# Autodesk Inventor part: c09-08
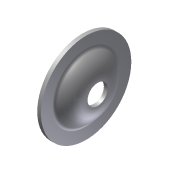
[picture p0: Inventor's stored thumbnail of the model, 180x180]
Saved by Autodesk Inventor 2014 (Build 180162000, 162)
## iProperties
Created: 2010-12
Part Number: c09-08
Document SubType Name: Modeling
Designer: Thom Tremblay
Density: 1 g/cm^3
Material: Generic
Appearance: Steel
Author: Thom Tremblay
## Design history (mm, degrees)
sketch "Sketch1"
  geometry: L1 (-1.246, 28.575)-(-1.246, 21.449); L2 (6.025, 7.188)-(6.025, 6.35); L3 (0, 0)-(18.611, 0); L4 (1.135, 28.575)-(1.135, 21.449); L5 (8.406, 7.188)-(8.406, 6.35); L6 (8.406, 6.35)-(6.025, 6.35); L7 (-1.246, 28.575)-(1.135, 28.575); A1 r 4.921 centre (3.675, 21.449) between (-1.246, 21.449) and (0.785, 17.467); A2 r 12.7 centre (-6.675, 7.188) between (6.025, 7.188) and (0.785, 17.467); A3 r 2.54 centre (3.675, 21.449) between (1.135, 21.449) and (2.183, 19.394); A4 r 15.081 centre (-6.675, 7.188) between (8.406, 7.188) and (2.183, 19.394)
  constraints: 14 end point, 8 point on circle, 5 tangent, 4 centre point, 3 parallel, 2 perpendicular, 1 vertical, 2 other
  dimensions: "d0" = 2.38125 distance between parallel lines of L4 L1; "d1" = 57.15 diameter of L1.start L3; "d2" = 12.7 diameter of L5.end L3; "d3" = 9.652 distance between parallel lines of L1 L5; "d4" = 12.7 radius of A2; "d5" = 2.54 radius of A3
revolve "Revolution1" sketch "Sketch1" stored, may be unused: angle "d6" = 90 deg
body "Solid1"
